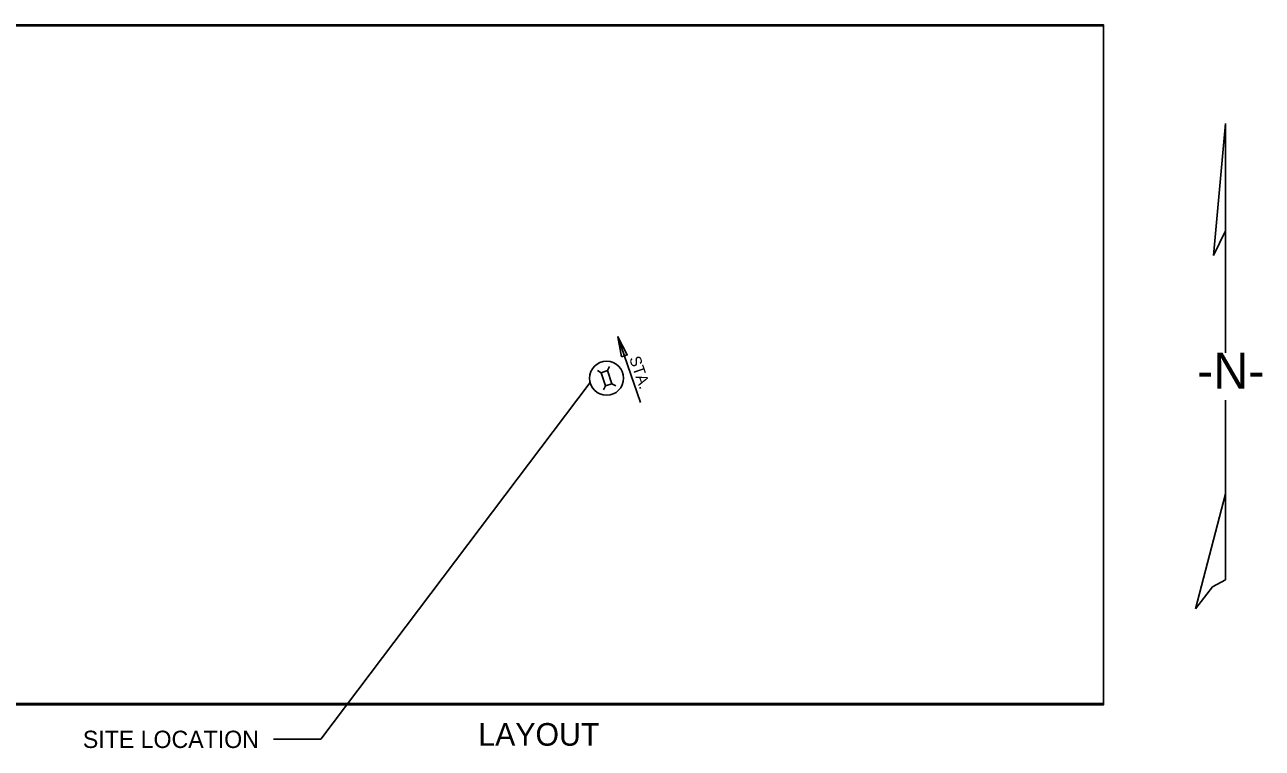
# Model space of a CAD drawing. Extents: x -4.82 to 4.15, y -0.44 to 2.32.
# Drawn here: x 1.007 to 2.146, y 0.503 to 1.169 of the extents above; entities that cross this region are included whole.
import ezdxf

# ---------------------------------------------------------------- set-up
doc = ezdxf.new("R2010")
doc.units = 0
for name, color, linetype in [('BR_AUTO DIMENSION', 7, 'Continuous'), ('BR_BORDER LINES', 7, 'Continuous'), ('BR_TEXT', 7, 'Continuous'), ('Default', 7, 'Continuous')]:
    doc.layers.add(name, color=color, linetype=linetype)

msp = doc.modelspace()

# ---------------------------------------------------------------- linework, layer by layer
at = {"layer": 'BR_AUTO DIMENSION'}
for p in [(1.5273, 0.8395), (1.2358, 0.511)]:
    msp.add_line(p, (1.2795, 0.511), dxfattribs=at)
msp.add_circle((1.5425, 0.8434), 0.0157, dxfattribs=at)
at = {"layer": 'BR_BORDER LINES'}
msp.add_lwpolyline([(0.9583, 0.5438), (2, 0.5438), (2, 1.1688), (0.9583, 1.1688)], close=True, dxfattribs=at)
at = {"layer": 'BR_TEXT'}
for p, q in [((1.5738, 0.8209), (1.5529, 0.8816)), ((1.5376, 0.8485), (1.534, 0.8505)), ((1.5435, 0.8504), (1.5452, 0.8541)), ((1.5415, 0.8364), (1.5398, 0.8327)), ((1.5474, 0.8383), (1.551, 0.8363))]:
    msp.add_line(p, q, dxfattribs=at)
for points in [[(1.5563, 0.8631), (1.5529, 0.8816), (1.5616, 0.8649)], [(1.5474, 0.8383), (1.5415, 0.8364), (1.5376, 0.8485), (1.5435, 0.8504)]]:
    msp.add_lwpolyline(points, close=True, dxfattribs=at)
at = {"layer": 'Default'}
for p, q in [((2.1013, 0.9564), (2.1124, 1.0778)), ((2.1124, 1.0778), (2.1124, 0.979)), ((2.1124, 0.979), (2.1013, 0.9564)), ((2.1124, 0.979), (2.1124, 0.9105)), ((2.1124, 0.9105), (2.1124, 0.8668)), ((2.1124, 0.8232), (2.1124, 0.7369)), ((2.0849, 0.6311), (2.1124, 0.7369)), ((2.1124, 0.7369), (2.1124, 0.7238)), ((2.1124, 0.7238), (2.1124, 0.6577))]:
    msp.add_line(p, q, dxfattribs=at)
msp.add_lwpolyline([(0.9583, 1.1677), (2, 1.1677), (2, 0.5427), (0.9583, 0.5427)], close=True, dxfattribs=at)
msp.add_lwpolyline([(2.1124, 0.6577), (2.1006, 0.6512), (2.0849, 0.6311)], dxfattribs=at)

# ---------------------------------------------------------------- texts
at = {"layer": 'BR_TEXT'}
for s, height, rotation, p in [('STA.', 0.01042, 289.0112, (1.5632, 0.8617)), ('SITE LOCATION ', 0.015922, 360, (1.0602, 0.503))]:
    msp.add_text(s, height=height, rotation=rotation, dxfattribs=at).set_placement(p)
at = {"layer": 'Default'}
for s, height, p in [('-N-', 0.03333, (2.0864, 0.8337)), ('LAYOUT', 0.02083, (1.4244, 0.5051))]:
    msp.add_text(s, height=height, dxfattribs=at).set_placement(p)

doc.saveas('drawing.dxf')
